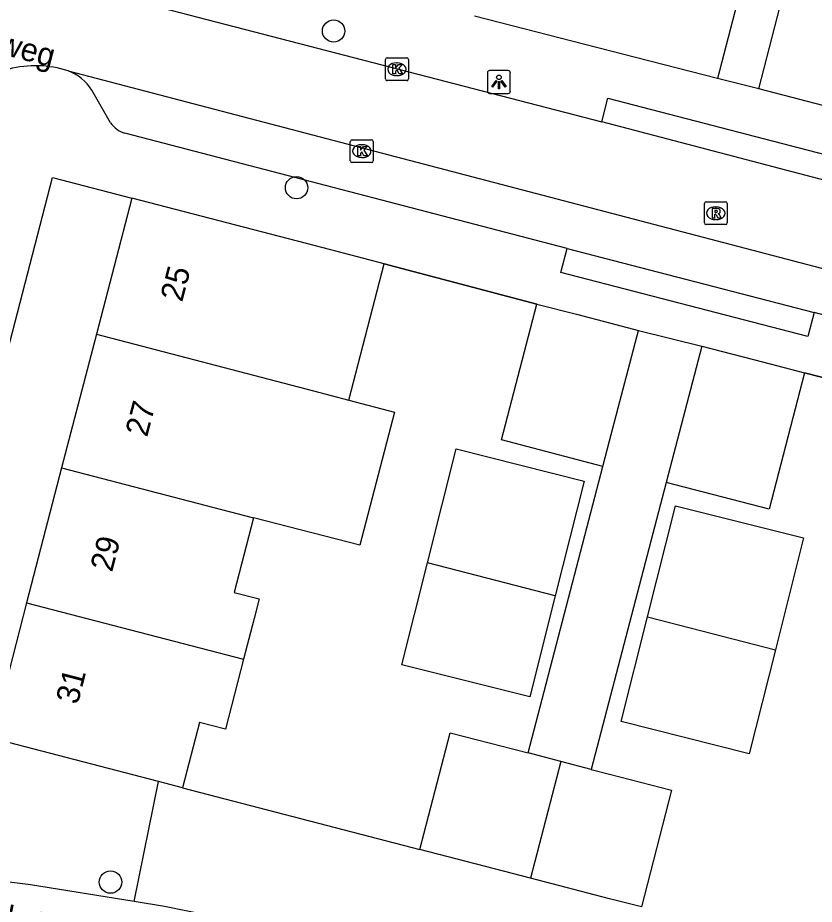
# Model space of a CAD drawing. Extents: x 163686 to 164493, y 382719 to 383870.
# Drawn here: x 163974.17 to 164008.93, y 383138.56 to 383177.27 of the extents above; entities that cross this region are included whole.
import ezdxf

# ---------------------------------------------------------------- set-up
doc = ezdxf.new("R2010")
doc.units = 0
for name, color, linetype in [('IMGEO_Boom', 7, 'Continuous'), ('IMGEO_Groenvoorziening', 7, 'Continuous'), ('IMGEO_Kolk', 7, 'Continuous'), ('IMGEO_Lichtpunt', 7, 'Continuous'), ('IMGEO_Muur', 7, 'Continuous'), ('IMGEO_Openbare_ruimte_label', 7, 'Continuous'), ('IMGEO_Pand', 7, 'Continuous'), ('IMGEO_Pand_nummerreeks', 7, 'Continuous'), ('IMGEO_Rijbaan_lokaal_open', 7, 'Continuous'), ('IMGEO_Rioolput', 7, 'Continuous'), ('IMGEO_Voetpad_halfverhard', 7, 'Continuous'), ('IMGEO_Voetpad_open', 7, 'Continuous')]:
    doc.layers.add(name, color=color, linetype=linetype)

msp = doc.modelspace()

# ---------------------------------------------------------------- linework, layer by layer
at = {"layer": 'IMGEO_Boom'}
for centre in [(163987.959, 383176.693), (163986.342, 383169.851), (163978.219, 383139.529)]:
    msp.add_circle(centre, 0.489, dxfattribs=at)
at = {"layer": 'IMGEO_Groenvoorziening'}
for points in [[(163979.255, 383138.674), (163980.317, 383143.919)], [(163981.37, 383143.646), (163991.719, 383140.951)]]:
    msp.add_lwpolyline(points, dxfattribs=at)
at = {"layer": 'IMGEO_Kolk'}
for p, q in [((163990.219, 383174.599), (163990.219, 383175.451)), ((163990.294, 383175.525), (163991.146, 383175.525)), ((163990.707, 383175.305), (163990.732, 383175.305)), ((163991.22, 383175.451), (163991.22, 383174.599)), ((163991.146, 383174.525), (163990.294, 383174.525)), ((163990.73, 383174.745), (163990.705, 383174.745)), ((163988.687, 383171.021), (163988.687, 383171.873)), ((163988.762, 383171.947), (163989.614, 383171.947)), ((163989.688, 383171.873), (163989.688, 383171.021)), ((163989.175, 383171.727), (163989.2, 383171.727)), ((163989.198, 383171.167), (163989.173, 383171.167)), ((163989.614, 383170.947), (163988.762, 383170.947))]:
    msp.add_line(p, q, dxfattribs=at)
for points in [[(163990.219, 383174.599), (163990.219, 383175.451)], [(163990.294, 383175.525), (163991.146, 383175.525)], [(163990.54, 383175.225), (163990.663, 383175.225), (163990.663, 383175.074), (163990.793, 383175.225), (163990.957, 383175.225), (163990.811, 383175.074), (163990.964, 383174.825), (163990.812, 383174.825), (163990.727, 383174.989), (163990.663, 383174.922), (163990.663, 383174.825), (163990.54, 383174.825), (163990.54, 383175.225)], [(163991.22, 383175.451), (163991.22, 383174.599)], [(163991.146, 383174.525), (163990.294, 383174.525)], [(163988.687, 383171.021), (163988.687, 383171.873)], [(163988.762, 383171.947), (163989.614, 383171.947)], [(163989.688, 383171.873), (163989.688, 383171.021)], [(163989.008, 383171.647), (163989.131, 383171.647), (163989.131, 383171.496), (163989.261, 383171.647), (163989.425, 383171.647), (163989.279, 383171.496), (163989.432, 383171.247), (163989.28, 383171.247), (163989.195, 383171.411), (163989.131, 383171.344), (163989.131, 383171.247), (163989.008, 383171.247), (163989.008, 383171.647)], [(163989.614, 383170.947), (163988.762, 383170.947)]]:
    msp.add_lwpolyline(points, dxfattribs=at)
for centre, start, end in [((163990.296, 383175.449), 91.552, 178.448), ((163990.296, 383175.449), 91.552, 178.448), ((163991.144, 383175.449), 1.552, 88.448), ((163991.144, 383175.449), 1.552, 88.448), ((163990.296, 383174.601), 181.552, 268.448), ((163990.296, 383174.601), 181.552, 268.448), ((163991.144, 383174.601), 271.552, 358.448), ((163991.144, 383174.601), 271.552, 358.448), ((163988.764, 383171.871), 91.552, 178.448), ((163988.764, 383171.871), 91.552, 178.448), ((163989.612, 383171.871), 1.552, 88.448), ((163989.612, 383171.871), 1.552, 88.448), ((163988.764, 383171.023), 181.552, 268.448), ((163988.764, 383171.023), 181.552, 268.448), ((163989.612, 383171.023), 271.552, 358.448), ((163989.612, 383171.023), 271.552, 358.448)]:
    msp.add_arc(centre, 0.0765, start, end, dxfattribs=at)
for centre, major_axis, ratio, start_param, end_param in [((163990.706, 383175.025), (-0.387, 0.002), 0.722429, 4.712389, 7.853982), ((163990.731, 383175.025), (-0.39, 0.002), 0.717154, 1.570796, 4.712389), ((163989.174, 383171.447), (-0.387, 0.002), 0.722429, 4.712389, 7.853982), ((163989.199, 383171.447), (-0.39, 0.002), 0.717154, 1.570796, 4.712389)]:
    msp.add_ellipse(centre, major_axis=major_axis, ratio=ratio, start_param=start_param, end_param=end_param, dxfattribs=at)
at = {"layer": 'IMGEO_Lichtpunt'}
for p, q in [((163994.674, 383174.872), (163994.674, 383174.065)), ((163994.674, 383174.872), (163994.674, 383174.065)), ((163995.576, 383174.967), (163994.768, 383174.967)), ((163995.576, 383174.967), (163994.768, 383174.967)), ((163995.67, 383174.065), (163995.67, 383174.872)), ((163995.67, 383174.065), (163995.67, 383174.872)), ((163994.768, 383173.971), (163995.576, 383173.971)), ((163994.768, 383173.971), (163995.576, 383173.971))]:
    msp.add_line(p, q, dxfattribs=at)
for points in [[(163995.048, 383174.536), (163995.087, 383174.508), (163994.899, 383174.246), (163994.861, 383174.273), (163995.048, 383174.536)], [(163995.15, 383174.488), (163995.197, 383174.488), (163995.197, 383174.166), (163995.15, 383174.166), (163995.15, 383174.488)], [(163995.26, 383174.508), (163995.298, 383174.535), (163995.485, 383174.273), (163995.446, 383174.245), (163995.26, 383174.508)]]:
    msp.add_lwpolyline(points, dxfattribs=at)
msp.add_circle((163995.173, 383174.67), 0.0994, dxfattribs=at)
for centre, start, end in [((163994.768, 383174.872), 90, 180), ((163994.768, 383174.872), 90, 180), ((163995.576, 383174.872), 0, 90), ((163995.576, 383174.872), 0, 90), ((163994.768, 383174.065), 180, 270), ((163994.768, 383174.065), 180, 270), ((163995.576, 383174.065), 270, 0), ((163995.576, 383174.065), 270, 360)]:
    msp.add_arc(centre, 0.0946, start, end, dxfattribs=at)
at = {"layer": 'IMGEO_Muur'}
for points in [[(163990.158, 383166.529), (163996.83, 383164.771)], [(164008.514, 383161.762), (164016.664, 383159.679)], [(163981.37, 383143.646), (163991.719, 383140.951)]]:
    msp.add_lwpolyline(points, dxfattribs=at)
at = {"layer": 'IMGEO_Pand'}
for points in [[(164006.393, 383181.13), (164004.716, 383174.612)], [(164006.512, 383174.162), (164008.145, 383180.506)], [(164004.716, 383174.612), (164000, 383175.823), (163994.1, 383177.336)], [(164010.032, 383173.256), (164006.512, 383174.162)], [(163979.145, 383169.396), (163977.604, 383163.456)], [(163990.158, 383166.529), (163987.504, 383167.228), (163979.145, 383169.396)], [(163988.615, 383160.579), (163990.158, 383166.529)], [(163999.71, 383157.681), (163995.29, 383158.836), (163996.83, 383164.771)], [(163996.83, 383164.771), (163998.556, 383164.323), (164000, 383163.949), (164001.26, 383163.621)], [(163999.71, 383157.681), (164000, 383158.793), (164001.26, 383163.621)], [(163977.604, 383163.456), (163976.088, 383157.611)], [(163977.604, 383163.456), (163987.078, 383160.981), (163988.615, 383160.579)], [(164004.028, 383162.933), (164002.476, 383156.984)], [(164004.028, 383162.933), (164006.672, 383162.243), (164008.514, 383161.762)], [(164008.514, 383161.762), (164006.962, 383155.812), (164002.476, 383156.984)], [(163988.615, 383160.579), (163990.617, 383160.055), (163989.108, 383154.238), (163984.464, 383155.441)], [(163992.056, 383153.474), (163993.303, 383158.441), (163998.889, 383157.038), (163997.631, 383152.03)], [(163976.088, 383157.611), (163974.56, 383151.722)], [(163976.088, 383157.611), (163984.464, 383155.441)], [(164001.662, 383151.108), (164002.881, 383155.961), (164008.467, 383154.558), (164007.24, 383149.673)], [(163984.464, 383155.441), (163983.618, 383152.177), (163984.711, 383151.893), (163984.49, 383151.041), (163984.03, 383149.269)], [(163997.631, 383152.03), (163996.521, 383147.61), (163990.935, 383149.013), (163992.056, 383153.474)], [(163997.631, 383152.03), (163992.056, 383153.474)], [(163974.56, 383151.722), (163973.026, 383145.81)], [(163974.56, 383151.722), (163984.03, 383149.269)], [(164007.24, 383149.673), (164006.099, 383145.13), (164000.513, 383146.533), (164001.662, 383151.108)], [(164001.662, 383151.108), (164007.24, 383149.673)], [(163984.03, 383149.269), (163983.234, 383146.201), (163982.109, 383146.493), (163981.37, 383143.646)], [(163980.317, 383143.919), (163973.026, 383145.81)], [(163991.719, 383140.951), (163993.042, 383146.048), (163996.444, 383145.165)], [(163997.875, 383144.794), (163996.444, 383145.165)], [(163997.875, 383144.794), (163996.555, 383139.697)], [(163999.199, 383144.451), (163997.875, 383144.794)], [(163999.199, 383144.451), (163999.997, 383144.244), (164002.702, 383143.546), (164001.391, 383138.443)], [(163981.37, 383143.646), (163980.317, 383143.919)], [(163996.555, 383139.697), (163994.973, 383140.107), (163991.719, 383140.951)], [(164001.391, 383138.443), (164000, 383138.803), (163996.555, 383139.697)]]:
    msp.add_lwpolyline(points, dxfattribs=at)
at = {"layer": 'IMGEO_Rijbaan_lokaal_open'}
for points in [[(163978.831, 383178.147), (163999.658, 383172.724)], [(163976.377, 383174.954), (164019.302, 383163.696), (164026.298, 383161.922)], [(164010.299, 383169.93), (163999.658, 383172.724)], [(164001.26, 383163.621), (164004.028, 383162.933)], [(163996.444, 383145.165), (163999.71, 383157.681)], [(164002.476, 383156.984), (163999.199, 383144.451)]]:
    msp.add_lwpolyline(points, dxfattribs=at)
msp.add_arc((163974.946, 383170.456), 4.72, 72.355, 104.2418, dxfattribs=at)
at = {"layer": 'IMGEO_Rioolput'}
for p, q in [((164004.138, 383168.311), (164004.138, 383169.163)), ((164004.213, 383169.237), (164005.065, 383169.237)), ((164005.139, 383169.163), (164005.139, 383168.311)), ((164004.626, 383169.017), (164004.651, 383169.017)), ((164004.649, 383168.457), (164004.624, 383168.457)), ((164005.065, 383168.237), (164004.213, 383168.237))]:
    msp.add_line(p, q, dxfattribs=at)
for points in [[(164004.138, 383168.311), (164004.138, 383169.163)], [(164004.213, 383169.237), (164005.065, 383169.237)], [(164005.139, 383169.163), (164005.139, 383168.311)], [(164004.727, 383168.935), (164004.475, 383168.937), (164004.475, 383168.537)], [(164004.475, 383168.537), (164004.599, 383168.537), (164004.599, 383168.699), (164004.61, 383168.699)], [(164004.653, 383168.856), (164004.599, 383168.856), (164004.599, 383168.775)], [(164004.599, 383168.775), (164004.651, 383168.775)], [(164004.657, 383168.67), (164004.728, 383168.537), (164004.868, 383168.537), (164004.803, 383168.663)], [(164005.065, 383168.237), (164004.213, 383168.237)]]:
    msp.add_lwpolyline(points, dxfattribs=at)
for centre, radius, start, end in [((164004.215, 383169.161), 0.0765, 91.552, 178.448), ((164004.215, 383169.161), 0.0765, 91.552, 178.448), ((164005.063, 383169.161), 0.0765, 1.552, 88.448), ((164005.063, 383169.161), 0.0765, 1.552, 88.448), ((164004.609, 383168.646), 0.0533, 26.0293, 88.6989), ((164004.635, 383168.964), 0.19, 274.7715, 282.9687), ((164004.659, 383168.76), 0.0964, 77.0061, 93.1865), ((164004.673, 383168.817), 0.0378, 276.6634, 79.6772), ((164004.726, 383168.825), 0.109, 350.3612, 89.416), ((164004.724, 383168.825), 0.112, 277.5842, 350.9817), ((164004.708, 383168.61), 0.108, 29.5134, 73.7905), ((164004.215, 383168.313), 0.0765, 181.552, 268.448), ((164004.215, 383168.313), 0.0765, 181.552, 268.448), ((164005.063, 383168.313), 0.0765, 271.552, 358.448), ((164005.063, 383168.313), 0.0765, 271.552, 358.448)]:
    msp.add_arc(centre, radius, start, end, dxfattribs=at)
for centre, major_axis, ratio, start_param, end_param in [((164004.625, 383168.737), (-0.387, 0.002), 0.722429, 4.712389, 7.853982), ((164004.65, 383168.737), (-0.39, 0.002), 0.717154, 1.570796, 4.712389)]:
    msp.add_ellipse(centre, major_axis=major_axis, ratio=ratio, start_param=start_param, end_param=end_param, dxfattribs=at)
at = {"layer": 'IMGEO_Voetpad_halfverhard'}
for points in [[(163979.255, 383138.674), (163974.734, 383139.412), (163968.854, 383140.139), (163962.954, 383140.638), (163961.861, 383140.822), (163960.768, 383141.256), (163959.759, 383141.944), (163958.92, 383142.853), (163958.314, 383143.913), (163957.969, 383145.037), (163957.872, 383146.141), (163957.967, 383152.728)], [(163986.383, 383137.276), (163980.581, 383138.456), (163979.255, 383138.674)]]:
    msp.add_lwpolyline(points, dxfattribs=at)
at = {"layer": 'IMGEO_Voetpad_open'}
for points in [[(164006.512, 383174.162), (164004.716, 383174.612)], [(163978.227, 383172.689), (163977.403, 383174.116)], [(163999.658, 383172.724), (163999.921, 383173.765), (164010.567, 383170.992), (164010.299, 383169.93)], [(163998.15, 383167.201), (163978.847, 383172.238)], [(163969.581, 383146.721), (163975.685, 383170.296), (163979.145, 383169.396)], [(164008.929, 383164.4), (164008.652, 383163.346), (163997.873, 383166.152), (163998.15, 383167.201)], [(163998.15, 383167.201), (164008.929, 383164.4)], [(163996.83, 383164.771), (163990.158, 383166.529)], [(164022.413, 383160.855), (164008.929, 383164.4)], [(164016.664, 383159.679), (164008.514, 383161.762)]]:
    msp.add_lwpolyline(points, dxfattribs=at)
for centre, radius, start, end in [((163975.557, 383172.903), 2.208, 33.3062, 68.2123), ((163979.123, 383173.269), 1.067, 212.9216, 255.0127)]:
    msp.add_arc(centre, radius, start, end, dxfattribs=at)

# ---------------------------------------------------------------- texts
at = {"layer": 'IMGEO_Openbare_ruimte_label'}
for s, rotation, p in [('Stobbaertsweg', 345.2273, (163967.026, 383177.377)), ('Cornelis de Vospad', 348.7013, (163967.976, 383138.656))]:
    msp.add_text(s, height=1, rotation=rotation, dxfattribs=at).set_placement(p)
at = {"layer": 'IMGEO_Pand_nummerreeks'}
for s, rotation, p in [('25', 75.4585, (163981.347, 383164.825)), ('27', 75.4585, (163979.817, 383158.928)), ('29', 75.4562, (163978.288, 383153.032)), ('31', 75.4562, (163976.787, 383147.244))]:
    msp.add_text(s, height=1, rotation=rotation, dxfattribs=at).set_placement(p)

doc.saveas('drawing.dxf')
